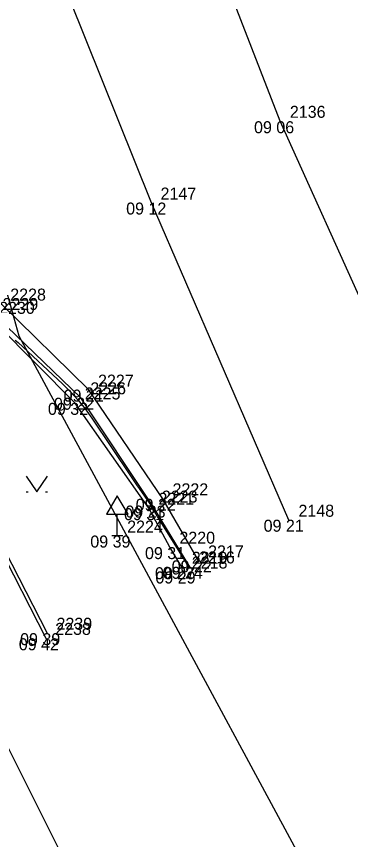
# Model space of a CAD drawing. Extents: x -703403 to -701924, y -1022520 to -1021856.
# Drawn here: x -702857.89 to -702850.09, y -1021972.4 to -1021953.17 of the extents above; entities that cross this region are included whole.
import ezdxf

# ---------------------------------------------------------------- set-up
doc = ezdxf.new("R2010")
doc.units = 0
for name, color, linetype in [('Ex_Minor Contours', 7, 'Continuous'), ('Z_body', 7, 'Continuous'), ('Z_body_cisla', 7, 'Continuous'), ('Z_body_vysky_redukovane', 7, 'Continuous'), ('Z_chodnik', 7, 'Continuous'), ('Z_dopravni_znacky', 7, 'Continuous'), ('Z_katastr_hranice', 7, 'Continuous'), ('Z_komunikace', 7, 'Continuous'), ('Z_obruba', 7, 'Continuous'), ('Z_rozhranni', 7, 'Continuous'), ('Z_vdz13_prerusovana', 7, 'Continuous'), ('Z_VDZ_25_prerus', 7, 'Continuous'), ('Z_znaky_kultur', 7, 'Continuous')]:
    doc.layers.add(name, color=color, linetype=linetype)

# ---------------------------------------------------------------- blocks, each defined once
blk = doc.blocks.new('POINT_DISPLAY')
blk.add_line((0, 0), (0, 0))
blk = doc.blocks.new('Z527')
for p, q in [((0, 0.93), (-0.25, 0.5)), ((0.25, 0.5), (0, 0.93)), ((-0.25, 0.5), (0.25, 0.5)), ((0, 0), (0, 0.5)), ((-0.13, 0), (0.13, 0))]:
    blk.add_line(p, q)
blk = doc.blocks.new('Z314')
for p, q in [((-0.25, 0.17), (0, -0.2)), ((0, -0.2), (0.25, 0.17)), ((-0.25, -0.2), (-0.2, -0.2)), ((0.2, -0.2), (0.25, -0.2))]:
    blk.add_line(p, q)

msp = doc.modelspace()

# ---------------------------------------------------------------- linework, layer by layer
at = {"layer": 'Ex_Minor Contours'}
msp.add_lwpolyline([(-702857.922, -1021960.731), (-702857.857, -1021960.791), (-702856.821, -1021961.755), (-702856.632, -1021961.94), (-702856.455, -1021962.136), (-702856.29, -1021962.341), (-702856.136, -1021962.557), (-702855.215, -1021963.928), (-702855.169, -1021963.997), (-702855.122, -1021964.066), (-702855.074, -1021964.135), (-702855.027, -1021964.204), (-702854.777, -1021964.562), (-702854.759, -1021964.589), (-702854.742, -1021964.616), (-702854.725, -1021964.644), (-702854.709, -1021964.672), (-702854.648, -1021964.786), (-702854.633, -1021964.814), (-702854.617, -1021964.842), (-702854.6, -1021964.87), (-702854.583, -1021964.897), (-702853.925, -1021965.95), (-702853.921, -1021965.957), (-702853.918, -1021965.965), (-702853.915, -1021965.973), (-702853.914, -1021965.982), (-702853.911, -1021966.025), (-702853.91, -1021966.029), (-702853.909, -1021966.033), (-702853.906, -1021966.035), (-702853.904, -1021966.038), (-702853.884, -1021966.052)], dxfattribs=at)
at = {"layer": 'Z_chodnik'}
msp.add_line((-702860.58, -1021961.11), (-702857.21, -1021967.7), dxfattribs=at)
at = {"layer": 'Z_katastr_hranice'}
for p, q in [((-702857.83, -1021960.64), (-702859.3, -1021955.41)), ((-702834.365, -1022004.133), (-702857.83, -1021960.64)), ((-702856.75, -1021972.93), (-702859.63, -1021967.18))]:
    msp.add_line(p, q, dxfattribs=at)
at = {"layer": 'Z_komunikace'}
for p, q in [((-702856.39, -1021962.08), (-702858.45, -1021960.1)), ((-702854.72, -1021964.6), (-702856.39, -1021962.08)), ((-702853.85, -1021966.03), (-702854.72, -1021964.6))]:
    msp.add_line(p, q, dxfattribs=at)
at = {"layer": 'Z_obruba'}
for p, q in [((-702856.53, -1021962.2), (-702858.52, -1021960.2)), ((-702860.51, -1021961.08), (-702857.18, -1021967.58)), ((-702854.8, -1021964.66), (-702856.53, -1021962.2)), ((-702854.31, -1021965.57), (-702854.8, -1021964.66)), ((-702854.03, -1021966.04), (-702854.31, -1021965.57)), ((-702854.02, -1021966.14), (-702854.03, -1021966.04))]:
    msp.add_line(p, q, dxfattribs=at)
at = {"layer": 'Z_rozhranni'}
for p, q in [((-702856.21, -1021961.89), (-702858.26, -1021959.88)), ((-702854.48, -1021964.44), (-702856.21, -1021961.89)), ((-702853.64, -1021965.88), (-702854.48, -1021964.44))]:
    msp.add_line(p, q, dxfattribs=at)
at = {"layer": 'Z_vdz13_prerusovana'}
for p, q in [((-702851.74, -1021955.62), (-702854.58, -1021948.28)), ((-702848.3, -1021963.24), (-702851.74, -1021955.62))]:
    msp.add_line(p, q, dxfattribs=at)
at = {"layer": 'Z_VDZ_25_prerus'}
for p, q in [((-702857.81, -1021949.88), (-702854.75, -1021957.52)), ((-702854.75, -1021957.52), (-702851.54, -1021964.93))]:
    msp.add_line(p, q, dxfattribs=at)

# ---------------------------------------------------------------- block references
at = {"layer": 'Z_body'}
for p in [(-702851.74, -1021955.62), (-702854.75, -1021957.52), (-702856.21, -1021961.89), (-702856.39, -1021962.08), (-702856.53, -1021962.2), (-702854.48, -1021964.44), (-702854.8, -1021964.66), (-702854.72, -1021964.6), (-702851.54, -1021964.93), (-702855.54, -1021965.3), (-702854.31, -1021965.57), (-702854.03, -1021966.04), (-702853.85, -1021966.03), (-702853.64, -1021965.88), (-702854.02, -1021966.14), (-702857.18, -1021967.58), (-702857.21, -1021967.7)]:
    msp.add_blockref('POINT_DISPLAY', p, dxfattribs=at)
at = {"layer": 'Z_dopravni_znacky'}
msp.add_blockref('Z527', (-702855.54, -1021965.3), dxfattribs=at)
at = {"layer": 'Z_znaky_kultur'}
msp.add_blockref('Z314', (-702857.42, -1021964.08), dxfattribs=at)

# ---------------------------------------------------------------- texts
at = {"layer": 'Z_body_cisla'}
for s, p in [('2136', (-702851.51, -1021955.54)), ('2147', (-702854.53, -1021957.45)), ('2228', (-702858.04, -1021959.81)), ('2230', (-702858.3, -1021960.12)), ('2229', (-702858.22, -1021960.03)), ('2227', (-702855.99, -1021961.82)), ('2226', (-702856.17, -1021962)), ('2225', (-702856.3, -1021962.12)), ('2222', (-702854.25, -1021964.36)), ('2221', (-702854.58, -1021964.58)), ('2223', (-702854.5, -1021964.53)), ('2148', (-702851.31, -1021964.86)), ('2224', (-702855.31, -1021965.23)), ('2220', (-702854.09, -1021965.49)), ('2217', (-702853.42, -1021965.81)), ('2219', (-702853.8, -1021965.96)), ('2218', (-702853.8, -1021966.07)), ('2216', (-702853.63, -1021965.95)), ('2238', (-702856.99, -1021967.62)), ('2239', (-702856.96, -1021967.5))]:
    msp.add_text(s, height=0.28, dxfattribs=at).set_placement(p)
at = {"layer": 'Z_body_vysky_redukovane'}
for s, p in [('09 06', (-702852.347, -1021955.9)), ('09 12', (-702855.333, -1021957.8)), ('09 21', (-702856.793, -1021962.17)), ('09 32', (-702857.16, -1021962.48)), ('09 22', (-702857.02, -1021962.36)), ('09 22', (-702855.11, -1021964.72)), ('09 31', (-702855.383, -1021964.94)), ('09 23', (-702855.35, -1021964.88)), ('09 21', (-702852.123, -1021965.21)), ('09 39', (-702856.17, -1021965.58)), ('09 31', (-702854.893, -1021965.85)), ('09 27', (-702854.66, -1021966.32)), ('09 24', (-702854.48, -1021966.31)), ('09 22', (-702854.27, -1021966.16)), ('09 29', (-702854.65, -1021966.42)), ('09 39', (-702857.81, -1021967.86)), ('09 42', (-702857.84, -1021967.98))]:
    msp.add_text(s, height=0.28, dxfattribs=at).set_placement(p)

doc.saveas('drawing.dxf')
